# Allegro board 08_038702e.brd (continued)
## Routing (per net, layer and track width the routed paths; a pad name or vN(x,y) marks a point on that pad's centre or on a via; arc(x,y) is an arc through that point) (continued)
IO_25_12_JX4: length 68.8
  TOP w0.14: U1.W17 v1(28.22,26.59)
  L4_SIG w0.095: v3(80.22,45.07) 80.12,44.97 74.09,44.97 73.71,44.59 73.71,44.05 73.33,43.67 57.28,43.67 57.13,43.82 54.81,43.82 54.66,43.67 54.15,43.67 54.03,43.54 53.39,43.54 53.1,43.84 50,43.84 49.99,43.82 49.65,43.82 49.45,43.62 49.45,43.29 48.31,42.15 43.99,42.15 43.61,41.76 43.61,40.37 43.36,40.11 41.2,40.11 40.56,39.47 40.56,39.45 40.36,39.25 40.34,39.25 39.88,38.79 39.88,38.66 39.14,37.93 39.07,37.93 38.88,37.73 38.88,37.66 38.46,37.25 37.32,37.25 37.14,37.07 30.02,37.07 29.89,36.93 29.07,36.93 28.74,36.6 28.7,36.6 28.21,36.1 28.21,36.06 27.88,35.73 27.88,34.92 27.74,34.78 27.74,26.97 28.12,26.59 v1(28.22,26.59)
  L19_GND w0.203: v3(80.22,45.07) 80.82,45.07 v4(80.82,45.07)
IO_25_13_JX2: length 72.3
  TOP w0.14: U1.V18 v1(29.22,25.59)
  L18_SIG w0.095: v1(35.36,8.24) 35.33,8.26 33.48,8.26 31.93,6.71 31.93,6.46 32.06,6.33 32.56,6.33 33.96,7.73 34.47,7.73 34.72,7.48 34.72,7.34 33.83,6.46 33.83,6.17 33.93,6.08 34.85,6.08 35.36,6.59 40.69,6.59 40.82,6.46 40.82,6.18 40.69,6.05 35.87,6.05 35.26,5.44 32.31,5.44 31.04,6.71 28.8,6.71 28.16,6.08 27.48,6.08 27.23,6.33 26.09,6.33 24.55,7.87 24.52,7.87 24.33,8.07 24.33,8.09 24.18,8.24 24.18,9.13 23.8,9.51 23.29,9.51 22.91,9.89 22.91,10.6 23.29,10.98 24.77,10.98 25.71,11.92 28.47,11.92 28.64,11.75 28.71,11.68 30.8,11.68 31.17,12.05 31.17,13.06 30.79,13.44 30.28,13.44 29.52,14.21 29.52,14.59 28.33,15.77 28.33,16.63 28.13,16.83 27.02,16.83 26.6,17.25 26.6,18.69 26.36,18.93 24.92,18.93 24.56,19.29 24.56,23.42 25.07,23.93 25.36,23.93 25.55,24.13 25.55,24.41 26.4,25.25 28.36,25.25 28.36,25.25 28.88,25.25 v1(29.22,25.59)
  BOTTOM w0.14: v1(35.36,8.24) 35.49,8.24 35.93,7.79 JX2.14
IO_25_33_JX1: length 72.6
  TOP w0.14: U1.N8 v1(35.22,36.59)
  L7_SIG w0.095: v1(34.33,49.65) 34.34,49.67 34.34,53.7 33.96,54.08 31.42,54.08 30.53,54.97 30.53,57.89 30.91,58.27 33.23,58.27 33.25,58.3 33.53,58.3 33.55,58.27 37.26,58.27 37.64,58.66 37.64,59.42 37.26,59.8 29.81,59.8 29.56,59.54 27.36,59.54 26.98,59.16 24.44,59.16 24.06,59.54 22.28,59.54 21.9,59.16 21.9,58.4 22.4,57.89 29.26,57.89 29.52,57.64 29.52,54.72 30.41,53.83 33.58,53.83 33.96,53.45 33.96,49.13 34.33,48.76 34.33,45.15 34.26,45.08 34.26,44.8 34.33,44.73 34.33,39.84 33.71,39.22 33.71,38.1 v1(35.22,36.59)
  BOTTOM w0.14: JX1.10 v1(34.33,49.65)
IO_25_34_JX4: length 50.5
  TOP w0.14: U1.K10 v1(38.22,34.59)
  L14_SIG w0.095: v1(38.22,34.59) 38.22,34.59 38.66,34.14 44.25,34.14 44.56,34.45 44.56,34.45 45.26,35.16 50.37,35.16 50.45,35.08 50.73,35.08 50.82,35.16 51.17,35.16 51.25,35.08 51.53,35.08 51.62,35.16 59.21,35.16 59.85,35.8 68.89,35.8 71.81,32.87 75.24,32.87 78.67,29.45 78.67,27.3 v1(80.2,25.77)
  BOTTOM w0.14: JX4.64 v1(80.2,25.77)
IO_25_35_AD9361_CLKOUT: length 31.8
  TOP w0.14: v6(66,32.09) U17.J6 ; U1.K12 v1(38.22,32.59)
  L4_SIG w0.095: v1(38.22,32.59) 38.82,31.99 39.17,31.99 39.23,31.93 39.36,31.93 39.55,31.73 39.55,31.6 41.07,30.08 47.55,30.08 48.82,31.35 53.93,31.35 54.14,31.14 54.42,31.14 54.63,31.35 56.72,31.35 56.85,31.22 57.06,31.01 57.34,31.01 57.56,31.22 59.74,31.22 60.12,30.84 63.85,30.84 64.7,31.69 65.59,31.69 v6(66,32.09)
IO_L01_12_JX3_N: length 72.3
  TOP w0.089: U1.Y11 v1(27.22,33.59)
  L18_SIG w0.089: v1(27.22,33.59) 26.81,33.18 20.34,33.18 19.99,32.83 19.99,32.34 20.34,32 25.35,32 25.58,31.77 25.58,31.6 25.55,31.58 25.55,31.45 25.35,31.25 25.23,31.25 25.2,31.22 19.98,31.22 19.61,30.85 19.61,30.33 19.98,29.95 25.33,29.95 25.55,29.73 25.55,29.42 25.33,29.19 20.63,29.19 20.25,28.81 20.25,28.3 20.62,27.93 25.35,27.93 25.55,27.73 25.55,27.38 25.35,27.18 20.77,27.18 20.25,26.65 20.25,25.11 19.95,24.81 19.95,24.35 19.75,24.16 17.42,24.16 17.07,23.81 17.07,23.32 17.42,22.97 18.74,22.97 18.98,22.74 18.98,22.31 18.74,22.08 15.69,22.08 15.17,21.56 15.17,20.82 15.69,20.3 18.75,20.3 18.98,20.08 18.98,19.76 18.59,19.38 18.59,18.76 18.36,18.52 17.81,18.52 17.58,18.76 17.58,19.01 17.05,19.54 16.23,19.54 15.2,18.5 14.53,18.5 14.15,18.88 v1(14.15,19.06)
  BOTTOM w0.089: JX3.22 13.17,19.37 13.49,19.06 v1(14.15,19.06)
IO_L01_12_JX3_P: length 72.3
  TOP w0.089: U1.Y12 v1(27.22,32.59)
  L18_SIG w0.089: v1(13.77,18.65) 13.98,18.65 14.49,18.14 14.66,18.14 14.76,18.25 15.3,18.25 16.34,19.29 16.94,19.29 17.32,18.9 17.32,18.65 17.71,18.27 18.47,18.27 18.85,18.65 18.85,19.28 19.23,19.66 19.23,20.18 18.86,20.56 15.79,20.56 15.42,20.93 15.42,21.45 15.79,21.83 18.85,21.83 19.23,22.21 19.23,22.84 18.85,23.22 17.52,23.22 17.32,23.42 17.32,23.7 17.52,23.9 19.86,23.9 20.2,24.25 20.2,24.7 20.5,25 20.5,26.55 20.88,26.93 25.46,26.93 25.81,27.27 25.81,27.83 25.46,28.18 20.73,28.18 20.5,28.41 20.5,28.71 20.73,28.94 25.43,28.94 25.81,29.31 25.81,29.83 25.43,30.21 20.09,30.21 19.86,30.43 19.86,30.75 20.09,30.97 25.3,30.97 25.33,31 25.46,31 25.81,31.34 25.81,31.47 25.83,31.5 25.83,31.88 25.46,32.25 20.44,32.25 20.25,32.45 20.25,32.73 20.44,32.93 26.88,32.93 v1(27.22,32.59)
  BOTTOM w0.089: JX3.20 13.18,18.57 13.45,18.84 13.58,18.84 v1(13.77,18.65)
IO_L01_13_JX2_N: length 72.9
  TOP w0.089: U1.AB25 v1(25.22,18.59)
  L18_SIG w0.089: v1(25.22,18.59) 25.59,18.22 25.59,18.13 25.55,18.09 25.55,17.45 25.35,17.25 23.14,17.25 23.14,17.25 23.08,17.25 22.88,17.45 22.88,17.73 22.91,17.76 22.91,18.42 22.88,18.45 22.88,18.73 22.91,18.76 22.91,19.42 22.88,19.45 22.88,19.73 22.91,19.76 22.91,20.42 22.88,20.45 22.88,20.73 22.91,20.76 22.91,21.42 22.88,21.45 22.88,21.73 22.91,21.76 22.91,22.42 22.88,22.45 22.88,22.68 22.81,22.76 22.81,22.83 22.46,23.18 22.38,23.18 21.9,23.18 21.63,22.91 21.63,16.22 21.52,16.11 21.36,16.11 21.27,16.03 20.99,16.03 20.91,16.11 19.83,16.11 19.75,16.03 19.47,16.03 19.39,16.11 17.96,16.11 17.71,15.86 17.71,15.22 17.96,14.97 24.46,14.97 24.56,14.86 24.56,14.44 24.46,14.33 18.02,14.33 17.87,14.19 17.54,14.19 17.35,14.38 16.93,14.38 16.85,14.46 13.01,14.46 12.75,14.21 12.75,13.32 13.01,13.06 26.5,13.06 26.88,13.44 26.88,16.01 26.98,16.11 27.54,16.11 27.61,16.04 27.61,14.97 28.08,14.5 28.47,14.5 28.63,14.35 v3(28.63,12.55)
  L19_GND w0.089: v3(28.63,12.55) 28.75,12.43 v4(28.75,12.05)
  BOTTOM w0.089: JX2.3 31.93,10.14 31.68,9.89 31.68,9.51 31.29,9.13 30.41,9.13 28.88,10.65 28.88,11.92 v4(28.75,12.05)
IO_L01_13_JX2_P: length 72.8
  TOP w0.089: U1.AA25 v1(26.22,18.59)
  L18_SIG w0.089: v1(26.22,18.59) 25.84,18.22 25.84,18.02 25.81,17.98 25.81,17.34 25.46,17 23.04,17 22.97,17 22.63,17.34 22.63,17.83 22.66,17.87 22.66,18.31 22.63,18.34 22.63,18.83 22.66,18.87 22.66,19.31 22.63,19.34 22.63,19.83 22.66,19.87 22.66,20.31 22.63,20.34 22.63,20.83 22.66,20.87 22.66,21.31 22.63,21.34 22.63,21.83 22.66,21.87 22.66,22.31 22.63,22.34 22.63,22.58 22.55,22.65 22.55,22.73 22.35,22.92 22.28,22.92 22.02,22.93 21.88,22.78 21.88,16.12 21.62,15.86 21.46,15.86 21.38,15.77 20.89,15.77 20.81,15.86 19.94,15.86 19.86,15.77 19.37,15.77 19.28,15.86 18.06,15.86 17.96,15.75 17.96,15.33 18.06,15.22 24.56,15.22 24.82,14.97 24.82,14.33 24.56,14.08 18.12,14.08 17.98,13.93 17.43,13.93 17.24,14.12 16.83,14.12 16.74,14.21 13.11,14.21 13.01,14.1 13.01,13.42 13.11,13.32 26.39,13.32 26.62,13.55 26.62,16.11 26.88,16.36 27.66,16.36 27.66,16.35 27.87,16.14 27.87,15.07 28.18,14.75 28.58,14.75 28.88,14.45 28.88,13.44 29.14,13.19 29.52,13.19 29.64,13.06 29.64,12.94 v3(29.26,12.55)
  L19_GND w0.089: v3(29.26,12.55) 29.1,12.39 v4(29.1,12.05)
  BOTTOM w0.089: v4(29.1,12.05) 29.1,10.74 30.49,9.34 31.2,9.34 31.46,9.6 31.46,9.88 31.13,10.21 JX2.1
IO_L01_33_JX1_N: length 72.3
  TOP w0.089: U1.F4 v1(42.22,40.59)
  L3_SIG w0.089: v1(42.22,40.59) 41.84,40.96 41.84,43.83 42.32,44.3 42.96,44.3 43.51,44.86 43.51,45.24 45.13,46.86 45.25,46.86 46.31,47.91 47.09,47.91 49.2,50.02 66.22,50.02 66.6,50.4 66.6,53.12 66.81,53.33 66.81,53.65 67.09,53.93 67.09,54.68 66.73,55.05 66.73,55.5 67.11,55.88 67.24,55.88 67.62,56.26 67.62,56.73 67.24,57.11 67.02,57.11 66.88,57.26 66.88,57.56 67.36,58.04 67.36,58.78 66.98,59.16 63.77,59.16 63.69,59.08 59.72,59.08 59.53,58.89 57.86,58.89 57.33,59.42 56.44,59.42 56.06,59.04 56.06,58.13 55.83,57.89 55.4,57.89 55.17,58.13 55.17,58.91 54.79,59.29 53.86,59.29 53.47,58.91 53.47,58.01 53.28,57.81 53.27,57.81 53.12,57.66 53.12,55.99 52.74,55.61 45.65,55.61 45.26,55.99 45.26,56.62 v1(45.52,56.88)
  BOTTOM w0.089: v1(45.52,56.88) 45.26,56.62 45.26,56.37 45.53,56.11 JX1.37
IO_L01_33_JX1_P: length 72.3
  TOP w0.089: U1.G4 v1(41.22,40.59)
  L3_SIG w0.089: v1(44.76,56.88) 45.01,56.62 45.01,55.88 45.54,55.35 52.84,55.35 53.37,55.88 53.37,57.55 53.73,57.9 53.73,58.8 53.96,59.04 54.68,59.04 54.92,58.8 54.92,58.02 55.3,57.64 55.93,57.64 56.31,58.02 56.31,58.93 56.55,59.16 57.22,59.16 57.75,58.64 59.63,58.64 59.82,58.83 63.8,58.83 63.88,58.91 66.88,58.91 67.11,58.68 67.11,58.15 66.62,57.66 66.62,57.15 66.92,56.86 67.13,56.86 67.36,56.62 67.36,56.37 67.13,56.14 67,56.14 66.47,55.61 66.47,54.94 66.84,54.58 66.84,54.04 66.56,53.75 66.56,53.44 66.35,53.23 66.35,50.51 66.11,50.27 49.1,50.27 46.99,48.17 46.21,48.17 45.15,47.11 45.02,47.11 43.25,45.34 43.25,44.96 42.85,44.56 42.22,44.56 41.59,43.93 41.59,40.96 v1(41.22,40.59)
  BOTTOM w0.089: JX1.35 44.73,56.09 45.01,56.37 45.01,56.62 v1(44.76,56.88)
IO_L01_34_JX4_N: length 71.9
  TOP w0.089: U1.H11 v1(40.22,33.59)
  L17_SIG w0.089: v1(84.38,42.53) 84.38,42.78 84.13,43.03 83.92,43.03 83.85,42.96 83.62,42.96 83.54,43.03 83.26,43.03 82.48,43.82 82.48,47.84 82.39,47.93 82.39,48.6 82.3,48.7 82.3,52 81.23,53.07 80.57,53.07 80.06,52.56 79.05,52.56 78.54,53.07 77.52,53.07 76.31,51.85 75.11,51.85 75.1,51.84 74.61,51.84 74.6,51.85 72.27,51.85 72.2,51.92 69.05,51.92 69,51.87 68.46,51.87 68.4,51.92 65.14,51.92 65,51.78 64.46,51.78 64.35,51.88 58.12,51.88 58.08,51.84 57.59,51.84 57.55,51.88 50.86,51.88 50.82,51.92 48.93,51.92 45.14,48.14 45.14,47.37 43.72,45.96 41.49,45.96 40.61,45.08 40.61,44.88 39.84,44.11 39.84,33.96 v1(40.22,33.59)
  BOTTOM w0.089: JX4.21 85.01,42.57 84.78,42.8 84.65,42.8 v1(84.38,42.53)
IO_L01_34_JX4_P: length 72
  TOP w0.089: U1.J11 v1(39.22,33.59)
  L17_SIG w0.089: v1(84.38,43.29) 83.36,43.29 82.73,43.92 82.73,47.95 82.65,48.03 82.65,48.71 82.55,48.81 82.55,52.1 81.33,53.32 80.46,53.32 79.96,52.81 79.15,52.81 78.64,53.32 77.42,53.32 76.2,52.11 75.01,52.11 74.99,52.1 74.72,52.1 74.7,52.11 72.37,52.11 72.3,52.18 68.94,52.18 68.89,52.13 68.56,52.13 68.51,52.18 65.04,52.18 64.89,52.03 64.56,52.03 64.46,52.14 58.02,52.14 57.98,52.1 57.7,52.1 57.66,52.14 50.96,52.14 50.92,52.18 48.82,52.18 44.88,48.24 44.88,47.48 43.61,46.21 41.38,46.21 40.36,45.18 40.36,44.98 39.59,44.22 39.59,33.96 v1(39.22,33.59)
  BOTTOM w0.089: v1(84.38,43.29) 84.63,43.03 84.76,43.03 85.1,43.37 JX4.19
IO_L01_35_RX_D0_N: length 43.1
  TOP w0.089: U1.E12 v1(43.22,32.59) ; v6(61.2,32.89) U17.K11
  L4_SIG w0.089: v1(43.22,32.59) 43.13,32.67 42.95,32.67 42.87,32.59 42.87,32.24 42.8,32.17 42.55,31.92 40.92,31.92 40.82,31.82 40.82,31.36 40.92,31.25 42.58,31.25 42.85,30.98 42.85,30.71 42.98,30.59 43.16,30.59 43.28,30.71 43.28,31.18 43.55,31.45 43.55,31.83 43.97,32.25 44.46,32.25 44.88,31.83 44.88,31.45 45.08,31.25 45.16,31.25 45.16,31.25 45.62,31.25 45.9,30.98 45.9,30.72 46.03,30.59 46.48,30.59 46.61,30.72 46.61,30.98 46.89,31.25 47.88,31.25 47.98,31.36 47.98,31.76 48.31,32.09 51.94,32.09 52.2,32.34 52.2,32.93 52.47,33.2 52.89,33.2 53.16,32.93 53.16,32.21 53.29,32.09 53.52,32.09 53.65,32.21 53.65,33.49 53.92,33.76 54.77,33.76 55.04,33.49 55.04,31.96 55.17,31.83 56.31,31.83 56.44,31.96 56.44,33.51 56.69,33.76 57.2,33.76 57.46,33.51 57.46,32.04 57.56,31.93 57.99,31.93 58.09,32.04 58.09,33.51 58.35,33.76 59.9,33.76 60.15,33.52 60.15,33.17 59.9,32.93 59.49,32.93 59.36,32.8 59.36,31.88 59.48,31.76 59.65,31.76 59.77,31.88 59.77,32.32 60.04,32.59 60.76,32.59 60.94,32.42 61.32,32.42 61.39,32.49 61.39,32.7 v6(61.2,32.89)
IO_L01_35_RX_D0_P: length 43.2
  TOP w0.089: v6(60.4,32.09) U17.J12 ; U1.F12 v1(42.22,32.59)
  L4_SIG w0.089: v6(60.4,32.09) 60.57,31.92 60.69,31.92 60.82,32.05 60.82,32.18 60.66,32.34 60.15,32.34 60.02,32.21 60.02,31.77 59.75,31.5 59.38,31.5 59.11,31.77 59.11,32.9 59.38,33.18 59.8,33.18 59.89,33.28 59.89,33.41 59.8,33.51 58.45,33.51 58.35,33.4 58.35,31.93 58.09,31.68 57.46,31.68 57.2,31.93 57.2,33.4 57.1,33.51 56.8,33.51 56.69,33.4 56.69,31.85 56.42,31.58 55.06,31.58 54.79,31.85 54.79,33.38 54.66,33.51 54.03,33.51 53.9,33.38 53.9,32.11 53.62,31.83 53.19,31.83 52.91,32.11 52.91,32.82 52.78,32.95 52.58,32.95 52.45,32.82 52.45,32.24 52.05,31.83 48.42,31.83 48.24,31.65 48.24,31.25 47.98,31 46.99,31 46.86,30.87 46.86,30.61 46.59,30.33 45.92,30.33 45.65,30.61 45.65,30.87 45.52,31 45.06,31 44.97,31 44.63,31.34 44.63,31.73 44.35,32 44.08,32 43.81,31.73 43.81,31.34 43.54,31.08 43.54,30.61 43.26,30.33 42.87,30.33 42.6,30.61 42.6,30.87 42.47,31 40.82,31 40.57,31.25 40.57,31.92 40.82,32.18 41.81,32.18 41.82,32.19 42.46,32.19 42.62,32.35 42.62,32.58 42.5,32.7 42.32,32.7 v1(42.22,32.59)
IO_L02_12_JX3_N: length 72.4
  TOP w0.089: U1.AC11 v1(24.22,33.59)
  L6_SIG w0.089: v1(24.22,33.59) 24.56,33.24 24.56,33.12 24.37,32.93 24.08,32.93 23.88,32.73 23.88,32.32 23.74,32.18 20.9,32.18 20.07,31.35 19.12,31.35 18.74,30.97 15.69,30.97 14.02,29.3 14.02,22.18 13.6,21.76 13.54,21.76 13.01,21.23 13.01,10.37 12.77,10.14 12.48,10.14 12.24,10.37 12.24,10.63 11.71,11.16 10.16,11.16 10.08,11.24 8.82,11.24 8.48,10.89 8.48,10.4 8.59,10.29 8.59,7.86 8.34,7.6 7.93,7.6 7.67,7.86 7.67,8.49 7.42,8.74 4.48,8.74 4.37,8.85 4.37,9.66 4.48,9.76 7.4,9.76 7.8,10.16 7.8,15.5 8.03,15.73 8.46,15.73 8.69,15.5 8.69,15.37 9.22,14.84 10.24,14.84 10.34,14.75 10.83,14.75 10.92,14.84 11.71,14.84 12.24,15.37 12.24,21.23 11.75,21.72 11.54,21.72 11.33,21.72 11.23,21.83 11.08,21.83 10.97,21.72 10.69,21.72 v1(10.47,21.95)
  BOTTOM w0.089: JX3.27 8.96,21.77 9.2,21.53 9.58,21.53 9.7,21.66 9.79,21.66 9.83,21.7 10.21,21.7 v1(10.47,21.95)
IO_L02_12_JX3_P: length 72.4
  TOP w0.089: U1.AB12 v1(25.22,32.59)
  L6_SIG w0.089: v1(25.22,32.59) 24.87,32.94 24.74,32.94 24.67,32.87 24.67,32.57 24.24,32.14 24.06,32.14 23.85,31.93 21.01,31.93 20.18,31.1 19.23,31.1 18.85,30.72 15.8,30.72 14.28,29.19 14.28,22.08 13.7,21.51 13.64,21.51 13.26,21.13 13.26,10.27 12.88,9.89 12.37,9.89 11.99,10.27 11.99,10.52 11.61,10.9 10.05,10.9 9.97,10.99 8.93,10.99 8.73,10.79 8.73,10.51 8.85,10.4 8.85,7.75 8.44,7.35 7.82,7.35 7.42,7.75 7.42,8.39 7.31,8.49 4.37,8.49 4.12,8.74 4.12,9.76 4.37,10.01 7.29,10.01 7.55,10.27 7.55,15.6 7.93,15.98 8.56,15.98 8.94,15.6 8.94,15.48 9.32,15.09 10.35,15.09 10.44,15 10.72,15 10.82,15.09 11.61,15.09 11.99,15.48 11.99,21.13 11.65,21.47 11.54,21.47 10.62,21.47 v1(10.47,21.32)
  BOTTOM w0.089: v1(10.47,21.32) 10.34,21.44 9.79,21.44 9.67,21.32 9.2,21.32 8.85,20.97 JX3.25
IO_L02_13_JX2_N: length 72.8
  TOP w0.089: U1.AC26 v1(24.22,17.59)
  L7_SIG w0.089: v1(24.22,17.59) 24.55,17.93 24.55,21.73 24.35,21.93 24.35,21.93 24.32,21.95 23.14,21.95 23.12,21.93 23.08,21.93 22.88,21.73 22.88,21.45 23.15,21.18 23.46,21.18 23.88,20.76 23.88,19.31 23.5,18.93 22.02,18.93 21.88,18.78 21.88,13.38 22.11,13.15 25.06,13.15 25.99,12.22 26.35,12.22 26.56,12.43 27.52,12.43 27.75,12.19 29.62,12.19 30.66,11.16 32.2,11.16 32.59,11.54 39.42,11.54 39.8,11.16 39.8,10.35 39.42,9.97 39.02,9.97 38.79,9.74 38.79,6.97 39.04,6.71 39.42,6.71 39.68,6.46 39.68,4.3 39.93,4.05 43.74,4.05 43.99,3.79 43.99,3.18 43.59,2.78 38.81,2.78 38.41,3.18 38.41,5.46 38.3,5.57 38.05,5.57 37.64,5.97 37.64,6.86 37.54,6.97 36.4,6.97 35.99,7.37 35.99,9.59 35.61,9.97 32.29,9.97 31.55,9.23 31.55,9 31.68,8.87 31.93,8.87 32.06,8.74 32.06,8.49 31.93,8.36 31.68,8.36 31.55,8.24 31.55,8.11 v1(31.8,7.86)
  BOTTOM w0.089: JX2.4 31.93,7.35 31.68,7.6 31.68,7.73 v1(31.8,7.86)
IO_L02_13_JX2_P: length 72.8
  TOP w0.089: U1.AB26 v1(25.22,17.59)
  L7_SIG w0.089: v1(31.29,7.86) 31.29,9.34 32.18,10.22 35.72,10.22 36.25,9.69 36.25,7.47 36.5,7.22 37.64,7.22 37.9,6.97 37.9,6.08 38.15,5.82 38.41,5.82 38.66,5.57 38.66,3.28 38.91,3.03 43.49,3.03 43.74,3.28 43.74,3.69 43.63,3.79 39.82,3.79 39.42,4.19 39.42,6.35 39.32,6.46 38.94,6.46 38.53,6.86 38.53,9.84 38.91,10.22 39.32,10.22 39.55,10.46 39.55,11.05 39.32,11.28 32.69,11.28 32.31,10.9 30.55,10.9 29.52,11.94 27.65,11.94 27.41,12.17 26.67,12.17 26.46,11.96 25.88,11.96 24.96,12.89 22.01,12.89 21.62,13.27 21.62,18.89 21.92,19.18 23.39,19.18 23.62,19.41 23.62,20.66 23.35,20.93 23.04,20.93 22.62,21.34 22.62,21.83 22.97,22.18 23.01,22.18 23.04,22.21 24.42,22.21 24.45,22.18 24.46,22.18 24.81,21.83 24.81,18 v1(25.22,17.59)
  BOTTOM w0.089: v1(31.29,7.86) 31.42,7.73 31.42,7.6 31.13,7.31 JX2.2
IO_L02_33_JX1_N: length 73.9
  TOP w0.089: U1.D3 v1(44.22,41.59)
  L3_SIG w0.089: v1(47.93,57.39) 47.63,57.09 47.63,56.8 48.06,56.37 50.6,56.37 50.98,56.75 50.98,58.17 50.75,58.4 49.96,58.4 49.58,58.78 49.58,59.93 49.96,60.31 51.36,60.31 51.49,60.18 67.59,60.18 68.63,59.14 68.63,56.75 68.38,56.5 68.38,54.14 68.33,54.09 68.33,53.76 68.38,53.71 68.38,52.74 68.33,52.69 68.33,52.36 68.38,52.31 68.38,49.28 67.34,48.24 60.01,48.24 59.96,48.19 59.47,48.19 59.42,48.24 55.06,48.24 54.94,48.37 54.01,48.37 53.88,48.24 48.31,48.24 47.3,47.23 47.3,45.7 45.65,44.05 44.48,44.05 44.36,43.92 43.97,43.92 43.81,43.76 43.81,43.34 43.46,43 43.05,43 42.85,42.8 42.85,41.48 43.08,41.25 43.72,41.25 43.75,41.22 43.95,41.22 43.98,41.18 44.15,41.18 44.22,41.25 v1(44.22,41.59)
  BOTTOM w0.089: JX1.43 47.93,56.25 47.68,56.5 47.68,57.13 v1(47.93,57.39)
IO_L02_33_JX1_P: length 74
  TOP w0.089: U1.D4 v1(44.22,40.59)
  L3_SIG w0.089: v1(47.3,57.39) 47.38,57.3 47.38,56.69 47.95,56.12 50.7,56.12 51.23,56.65 51.23,58.27 50.85,58.66 50.07,58.66 49.84,58.89 49.84,59.82 50.07,60.05 51.25,60.05 51.38,59.93 67.49,59.93 68.38,59.04 68.38,56.86 68.12,56.6 68.12,54.25 68.07,54.2 68.07,53.65 68.12,53.6 68.12,52.85 68.07,52.8 68.07,52.26 68.12,52.21 68.12,49.38 67.24,48.5 59.9,48.5 59.85,48.44 59.57,48.44 59.52,48.5 55.17,48.5 55.04,48.62 53.9,48.62 53.77,48.5 48.21,48.5 47.04,47.33 47.04,45.81 45.54,44.3 44.38,44.3 44.25,44.18 43.87,44.18 43.55,43.86 43.55,43.45 43.35,43.25 42.94,43.25 42.6,42.91 42.6,41.37 42.97,41 43.61,41 43.65,40.96 43.84,40.96 v1(44.22,40.59)
  BOTTOM w0.089: JX1.41 47.13,56.2 47.42,56.5 47.42,57.13 47.3,57.26 v1(47.3,57.39)
IO_L02_34_JX4_N: length 74.2
  TOP w0.089: U1.G5 v1(41.22,39.59)
  L4_SIG w0.089: v1(41.22,39.59) 41.59,39.22 43.32,39.22 43.55,39.45 43.55,39.8 43.99,40.24 48.06,40.24 49.84,42.02 50.26,42.02 50.45,42.22 50.73,42.22 50.93,42.02 51.06,42.02 51.25,42.22 51.53,42.22 51.73,42.02 52.03,42.02 52.24,42.23 52.52,42.23 52.73,42.02 54.66,42.02 55.3,42.65 55.93,42.65 56.82,41.76 57.58,41.76 57.71,41.89 61.41,41.89 61.92,42.4 63.77,42.4 64.28,41.89 73.33,41.89 73.97,42.53 74.22,42.78 74.96,42.78 75.6,42.15 76.65,42.15 76.92,42.41 76.92,42.5 77.29,42.87 77.38,42.87 77.45,42.95 77.46,42.95 77.78,43.27 77.78,43.65 78.31,44.18 80.57,44.18 80.95,44.56 80.95,51.8 80.57,52.18 79.43,52.18 79.02,52.58 79.02,53.43 79.43,53.83 81.69,53.83 82.22,53.3 82.22,52.05 82.6,51.67 82.73,51.67 83.11,51.29 83.11,49.89 82.73,49.51 82.6,49.51 82.22,49.13 82.22,43.16 81.71,42.65 v1(80.19,42.65)
  BOTTOM w0.089: JX4.22 80.81,42.57 80.52,42.86 80.4,42.86 v1(80.19,42.65)
IO_L02_34_JX4_P: length 74.2
  TOP w0.089: U1.G6 v1(41.22,38.59)
  L4_SIG w0.089: v1(80.19,43.29) 80.19,43.13 80.41,42.91 80.7,42.91 80.82,43.03 80.82,43.42 80.95,43.54 81.21,43.54 81.33,43.42 81.33,43.03 81.46,42.91 81.61,42.91 81.97,43.27 81.97,49.24 82.5,49.77 82.62,49.77 82.86,50 82.86,51.18 82.62,51.42 82.5,51.42 81.97,51.95 81.97,53.19 81.59,53.58 79.53,53.58 79.28,53.32 79.28,52.69 79.53,52.43 80.68,52.43 81.21,51.9 81.21,44.45 80.68,43.92 78.41,43.92 78.03,43.54 78.03,43.16 77.56,42.69 77.56,42.69 77.48,42.62 77.4,42.62 77.17,42.4 77.17,42.3 76.76,41.89 75.49,41.89 74.86,42.53 74.33,42.53 74.07,42.27 73.44,41.64 64.17,41.64 63.67,42.15 62.03,42.15 61.52,41.64 57.96,41.64 57.79,41.46 56.33,41.46 56.28,41.42 56,41.42 55.88,41.54 55.05,41.54 54.98,41.6 54.82,41.76 52.73,41.76 52.52,41.55 52.24,41.55 52.03,41.76 51.75,41.76 51.53,41.54 51.25,41.54 51.03,41.76 50.95,41.76 50.73,41.54 50.45,41.54 50.23,41.76 49.94,41.76 48.16,39.99 44.1,39.99 43.81,39.69 43.81,39.34 43.42,38.96 41.59,38.96 v1(41.22,38.59)
  BOTTOM w0.089: JX4.20 80.78,43.37 80.51,43.1 80.38,43.1 v1(80.19,43.29)
IO_L02_35_RX_D1_N: length 43.8
  TOP w0.089: U1.D10 v1(44.22,34.59) ; v6(62,32.89) U17.K10
  L17_SIG w0.089: v6(62,32.89) 61.85,32.75 61.65,32.75 61.52,32.88 61.52,33 61.32,33.19 61.05,33.19 60.7,33.55 60.7,33.82 60.52,33.99 60.41,33.99 59.36,35.03 58.49,35.03 57.99,34.53 57.38,34.53 57.13,34.28 57.05,34.28 56.82,34.05 56.82,33.64 57.08,33.38 59.11,33.38 59.36,33.13 59.36,32.85 59.26,32.74 59.03,32.74 58.87,32.58 58.59,32.58 58.42,32.74 55.25,32.74 54.76,33.23 54.76,34.53 54.51,34.78 53.92,34.78 53.52,34.38 53.52,32.81 53.41,32.7 52.99,32.7 52.88,32.81 52.88,35.16 52.63,35.41 52,35.41 51.74,35.16 51.74,33.71 51.64,33.61 50.69,33.61 50.69,33.6 49.55,33.6 49.18,33.24 48.31,33.24 47.93,33.61 47.93,34.17 48.31,34.55 48.31,36.3 48.06,36.56 47.71,36.56 47.34,36.18 46.97,36.18 46.97,36.18 46.88,36.18 46.63,35.92 46.63,34.74 46.55,34.67 46.55,34.45 46.53,34.43 46.53,33.74 46.55,33.73 46.55,33.45 46.35,33.25 46.29,33.25 46.28,33.24 46.15,33.24 46.14,33.25 46.08,33.25 45.88,33.45 45.88,33.83 45.46,34.25 44.97,34.25 44.55,33.83 44.55,33.45 44.35,33.25 44.26,33.25 44.25,33.24 44.07,33.24 43.84,33.47 43.84,34.22 v1(44.22,34.59)
IO_L02_35_RX_D1_P: length 44.1
  TOP w0.089: v6(61.2,32.09) U17.J11 ; U1.E10 v1(43.22,34.59)
  L17_SIG w0.089: v6(61.2,32.09) 61.39,32.29 61.39,32.49 61.32,32.56 61.1,32.56 60.88,32.78 60.88,33 60.51,33.38 60.29,33.38 60.08,33.58 60.08,33.8 59.97,33.92 59.97,34.14 59.33,34.78 58.6,34.78 58.09,34.27 57.48,34.27 57.24,34.02 57.15,34.02 57.08,33.95 57.08,33.74 57.18,33.64 59.21,33.64 59.62,33.23 59.62,32.74 59.36,32.49 59.14,32.49 58.97,32.32 58.48,32.32 58.32,32.49 55.15,32.49 54.51,33.13 54.51,34.42 54.41,34.53 54.03,34.53 53.77,34.27 53.77,32.75 53.52,32.49 52.88,32.49 52.63,32.75 52.63,35.06 52.52,35.16 52.1,35.16 52,35.06 52,33.61 51.74,33.35 50.8,33.35 50.8,33.35 49.65,33.35 49.29,32.99 48.2,32.99 47.68,33.51 47.68,34.27 48.06,34.65 48.06,36.2 47.95,36.3 47.82,36.3 47.44,35.92 47.08,35.92 47.07,35.92 46.98,35.92 46.88,35.82 46.88,34.64 46.81,34.56 46.81,34.34 46.79,34.33 46.79,33.85 46.81,33.83 46.81,33.34 46.46,33 46.4,33 46.39,32.99 46.05,32.99 46.03,33 45.97,33 45.63,33.34 45.63,33.73 45.35,34 45.08,34 44.81,33.73 44.81,33.34 44.46,33 44.37,33 44.35,32.99 43.97,32.99 43.59,33.36 43.59,34.22 v1(43.22,34.59)
IO_L03_12_JX3_N: length 73.2
  TOP w0.089: U1.AA10 v1(26.22,34.59)
  L18_SIG w0.089: v1(26.22,34.59) 26.59,34.96 26.59,35.16 26.6,35.16 26.6,36.8 26.98,37.19 29.54,37.19 29.56,37.21 29.56,38.73 29.63,38.8 29.63,41.91 29.54,42 28.89,42 28.81,41.91 28.81,38.34 28.46,38 28.4,38 28.33,37.94 27.02,37.94 26.6,38.36 26.6,41.68 26.55,41.73 26.35,41.92 26.08,41.92 26.07,41.91 25.98,41.91 25.83,41.77 25.83,34.37 25.81,34.34 25.46,34 25.25,34 24.97,34 24.62,34.34 24.62,37.83 24.69,37.9 24.69,38.28 24.62,38.34 24.62,38.83 24.69,38.9 24.69,39.28 24.62,39.34 24.62,40.83 24.46,41 24.07,41 23.81,40.73 23.81,40.34 23.8,40.34 23.8,39.84 23.81,39.83 23.81,39.34 23.8,39.34 23.8,38.84 23.81,38.83 23.81,38.34 23.8,38.34 23.8,37.84 23.81,37.83 23.81,37.34 23.8,37.34 23.8,36.84 23.81,36.83 23.81,36.34 23.46,36 22.95,36 22.55,36.4 22.55,38.1 22.45,38.21 21.87,38.21 21.77,38.1 21.77,36.33 21.37,35.92 21.08,35.92 20.63,35.48 20.63,34.29 19.97,33.64 19.21,33.64 18.59,33.02 18.59,31.71 19.23,31.07 19.23,25.89 18.47,25.13 16.82,25.13 16.18,24.49 15.27,24.49 14.13,23.35 14.13,22.48 14.28,22.33 14.53,22.33 14.66,22.21 14.66,22.08 14.53,21.95 14.28,21.95 14.13,21.81 14.13,21.64 14.46,21.32 v1(14.66,21.32)
  BOTTOM w0.089: v1(14.66,21.32) 14.2,21.32 13.98,21.53 13.64,21.53 13.4,21.77 JX3.28
IO_L03_12_JX3_P: length 73.3
  TOP w0.089: U1.Y10 v1(27.22,34.59)
  L18_SIG w0.089: v1(14.28,20.94) 14.28,21.14 13.88,21.54 13.88,23.46 15.17,24.75 16.08,24.75 16.71,25.38 18.36,25.38 18.98,25.99 18.98,30.97 18.34,31.6 18.34,33.13 19.1,33.89 19.86,33.89 20.37,34.4 20.37,35.58 20.97,36.18 21.26,36.18 21.52,36.43 21.52,38.21 21.77,38.46 22.55,38.46 22.81,38.21 22.81,36.51 23.06,36.25 23.35,36.25 23.55,36.45 23.55,36.73 23.55,36.73 23.55,37.44 23.55,37.45 23.55,37.73 23.55,37.73 23.55,38.44 23.55,38.45 23.55,38.73 23.55,38.73 23.55,39.44 23.55,39.45 23.55,39.73 23.55,39.73 23.55,40.44 23.55,40.45 23.55,40.84 23.97,41.25 24.57,41.25 24.88,40.94 24.88,39.45 24.94,39.38 24.94,38.79 24.88,38.73 24.88,38.45 24.94,38.38 24.94,37.79 24.88,37.73 24.88,34.45 25.08,34.25 25.35,34.25 25.58,34.48 25.58,41.88 25.87,42.17 25.96,42.17 25.97,42.18 26.46,42.18 26.73,41.91 26.85,41.79 26.85,38.46 27.12,38.19 28.23,38.19 28.29,38.25 28.35,38.25 28.55,38.45 28.55,42.02 28.79,42.25 29.65,42.25 29.88,42.02 29.88,37.17 29.64,36.94 27.23,36.94 27.22,36.92 27.08,36.92 26.85,36.7 26.85,35.06 26.84,35.05 26.84,34.96 v1(27.22,34.59)
  BOTTOM w0.089: v1(14.28,20.94) 13.9,21.32 13.64,21.32 13.3,20.97 JX3.26
IO_L03_13_JX2_N: length 73.2
  TOP w0.089: U1.AE26 v1(22.22,17.59)
  L3_SIG w0.089: v1(30.28,14.46) 30.15,14.33 26.07,14.33 25.81,14.58 25.81,15.1 25.45,15.46 25.45,16.75 24.82,17.38 24.82,34.91 24.47,35.25 23.93,35.25 23.55,34.87 23.55,25.35 23.38,25.18 22.97,25.18 22.81,25.35 22.81,27.83 22.8,27.84 22.8,28.34 22.81,28.34 22.81,28.83 22.8,28.84 22.8,29.34 22.81,29.34 22.81,29.83 22.8,29.84 22.8,31.34 22.81,31.34 22.81,31.83 22.8,31.84 22.8,32.34 22.81,32.34 22.81,32.83 22.8,32.84 22.8,33.34 22.81,33.34 22.81,33.83 22.8,33.84 22.8,34.34 22.81,34.34 22.81,34.83 22.8,34.84 22.8,34.87 22.42,35.25 21.97,35.25 21.62,34.91 21.62,18.16 21.84,17.94 22.1,17.94 22.15,17.89 22.15,17.65 v1(22.22,17.59)
  L19_GND w0.089: v4(33.45,13.19) 33.33,13.32 33.33,13.49 33.4,13.57 33.4,13.72 33.33,13.8 33.33,13.95 32.95,14.33 30.41,14.33 v1(30.28,14.46)
  BOTTOM w0.089: JX2.7 33.53,11.95 33.36,12.12 33.36,13.09 v4(33.45,13.19)
IO_L03_13_JX2_P: length 73.3
  TOP w0.089: U1.AE25 v1(22.22,18.59)
  L3_SIG w0.089: v1(30.28,13.95) 30.15,14.08 25.96,14.08 25.56,14.48 25.56,14.99 25.2,15.35 25.2,16.64 24.56,17.28 24.56,34.8 24.37,35 24.04,35 23.81,34.77 23.81,25.24 23.49,24.93 22.87,24.93 22.55,25.24 22.55,27.73 22.55,27.73 22.55,28.45 22.55,28.45 22.55,28.73 22.55,28.73 22.55,29.45 22.55,29.45 22.55,29.73 22.55,29.73 22.55,31.45 22.55,31.45 22.55,31.73 22.55,31.73 22.55,32.45 22.55,32.45 22.55,32.73 22.55,32.73 22.55,33.45 22.55,33.45 22.55,33.73 22.55,33.73 22.55,34.45 22.55,34.45 22.55,34.73 22.55,34.73 22.55,34.77 22.32,35 22.08,35 21.88,34.8 21.88,18.27 21.95,18.2 22.2,18.2 22.4,17.99 22.52,17.99 22.67,18.14 22.67,18.51 22.53,18.65 22.28,18.65 v1(22.22,18.59)
  L19_GND w0.089: v1(30.28,13.95) 30.41,14.08 32.84,14.08 33.07,13.85 33.07,13.32 v4(32.95,13.19)
  BOTTOM w0.089: v4(32.95,13.19) 33.14,12.99 33.14,12.12 32.73,11.7 JX2.5
IO_L03_33_JX1_N: length 74
  TOP w0.089: U1.F2 v1(42.22,42.59)
  L4_SIG w0.089: v1(42.22,42.59) 41.84,42.22 41.84,41.16 41.61,40.92 41.08,40.92 40.81,40.65 40.81,40.34 40.39,39.92 40.08,39.92 39.88,39.73 39.88,39.42 39.39,38.92 39.08,38.92 38.88,38.73 38.88,38.42 38.42,37.95 36.01,37.95 35.63,38.34 35.63,38.47 35.56,38.53 35.56,45.5 36.12,46.06 36.12,46.36 35.63,46.84 32.4,46.84 32.32,46.93 32.04,46.93 31.96,46.84 30.02,46.84 29.77,47.1 29.77,47.86 30.02,48.11 37.35,48.11 37.63,48.39 38.17,48.39 38.44,48.11 38.88,48.11 39.15,48.39 39.69,48.39 39.97,48.11 40.4,48.11 40.68,48.39 41.22,48.39 41.49,48.11 41.86,48.11 41.96,48.22 41.96,48.9 41.86,49 33.96,49 33.71,49.26 33.71,51.54 33.96,51.8 36.35,51.8 36.73,51.42 37.28,51.42 37.67,51.8 40.92,51.8 41.33,51.39 41.33,50.51 41.43,50.4 42.87,50.4 42.98,50.51 42.98,53.07 43.23,53.32 44.38,53.32 44.63,53.07 44.63,52.05 44.88,51.8 47.68,51.8 47.93,51.54 v1(47.93,49.64)
  BOTTOM w0.089: v1(47.93,49.64) 47.61,49.96 47.61,50 47.93,50.32 JX1.44
IO_L03_33_JX1_P: length 73.9
  TOP w0.089: U1.G2 v1(41.22,42.59)
  L4_SIG w0.089: v1(47.17,49.64) 47.46,49.64 47.68,49.86 47.68,50.27 47.55,50.4 47.04,50.4 46.89,50.53 46.89,50.78 47.04,50.91 47.55,50.91 47.68,51.04 47.68,51.42 47.55,51.54 44.78,51.54 44.38,51.95 44.38,52.96 44.27,53.07 43.34,53.07 43.23,52.96 43.23,50.4 42.98,50.15 41.33,50.15 41.07,50.4 41.07,51.29 40.82,51.54 37.77,51.54 37.39,51.16 36.63,51.16 36.25,51.54 34.07,51.54 33.96,51.44 33.96,49.36 34.07,49.26 41.96,49.26 42.22,49 42.22,48.11 41.96,47.86 41.38,47.86 41.11,48.13 40.78,48.13 40.51,47.86 39.86,47.86 39.59,48.13 39.26,48.13 38.98,47.86 38.34,47.86 38.06,48.13 37.73,48.13 37.46,47.86 30.13,47.86 30.02,47.76 30.02,47.2 30.13,47.1 31.86,47.1 31.94,47.18 32.43,47.18 32.51,47.1 35.74,47.1 36.37,46.46 36.37,45.96 35.82,45.4 35.82,38.64 35.88,38.58 35.88,38.45 36.12,38.21 38.31,38.21 38.62,38.52 38.62,38.83 38.97,39.18 39.28,39.18 39.62,39.52 39.62,39.83 39.97,40.18 40.28,40.18 40.55,40.45 40.55,40.76 40.97,41.18 41.5,41.18 41.59,41.26 41.59,42.29 41.48,42.4 41.4,42.4 v1(41.22,42.59)
  BOTTOM w0.089: v1(47.17,49.64) 47.4,49.87 47.4,50.05 47.13,50.32 JX1.42
IO_L03_34_JX4_N: length 72.2
  TOP w0.089: U1.G9 v1(41.22,35.59)
  L17_SIG w0.089: v1(84.38,40.24) 84.19,40.05 84.06,40.05 84,40.11 84,40.37 83.75,40.62 82.88,40.62 81.55,41.95 81.55,44.18 81.17,44.56 81.08,44.56 80.7,44.94 80.7,46.72 81.08,47.1 81.17,47.1 81.55,47.48 81.55,48.68 81.23,49 80.44,49 79.68,48.24 79.17,48.24 78.79,48.62 78.79,51.69 78.43,52.05 77.88,52.05 76.9,51.07 62.79,51.07 61.74,50.02 61.14,50.02 60.09,51.07 50.23,51.07 48.81,49.65 48.81,48.25 48.43,47.87 46.4,47.87 46.26,47.74 46.26,47.27 44.48,45.49 42.49,45.49 40.82,43.82 40.82,36.18 40.84,36.16 40.84,35.96 v1(41.22,35.59)
  BOTTOM w0.089: v1(84.38,40.24) 84.55,40.41 84.76,40.41 85,40.17 JX4.27
IO_L03_34_JX4_P: length 72.6
  TOP w0.089: U1.H9 v1(40.22,35.59)
  L17_SIG w0.089: v1(40.22,35.59) 40.59,35.96 40.59,36.05 40.57,36.07 40.57,43.92 42.38,45.74 44.38,45.74 46.01,47.37 46.01,47.84 46.29,48.13 48.32,48.13 48.56,48.36 48.56,49.75 50.13,51.33 60.19,51.33 61.24,50.27 61.63,50.27 62.68,51.33 76.8,51.33 77.78,52.31 78.54,52.31 79.05,51.8 79.05,48.73 79.28,48.5 79.58,48.5 80.34,49.26 81.33,49.26 81.8,48.79 81.8,47.37 81.27,46.84 81.18,46.84 80.95,46.61 80.95,45.04 81.18,44.81 81.27,44.81 81.8,44.28 81.8,42.06 82.98,40.88 v1(84.38,40.88)
  BOTTOM w0.089: JX4.25 85.11,40.97 84.76,40.62 84.63,40.62 v1(84.38,40.88) ; v1(40.22,35.59) 39.98,35.35 R53.1
IO_L03_35_RX_D2_N: length 44.2
  TOP w0.089: U1.F10 v1(42.22,34.59) ; v6(62.8,32.89) U17.K9
  L17_SIG w0.089: v1(42.22,34.59) 41.84,34.22 41.84,33.86 41.87,33.84 41.87,33.44 42.07,33.24 42.36,33.24 42.6,33.48 42.6,34.63 42.61,34.65 42.61,34.84 42.97,35.19 45.39,35.19 45.63,35.43 45.63,35.83 45.65,35.85 45.65,36.32 45.63,36.34 45.63,36.83 46.04,37.25 47.35,37.25 47.55,37.45 48.49,37.45 48.89,37.04 48.89,35.39 49,35.29 49.63,35.29 50.09,35.75 50.09,36.43 50.34,36.68 50.73,36.68 50.98,36.43 50.98,36.26 51.23,36.01 51.74,36.01 52,36.26 52,36.94 52.25,37.19 53.01,37.19 53.27,36.94 53.27,36.26 53.52,36.01 54.79,36.01 55.04,35.75 55.04,35.42 55.25,35.21 55.53,35.21 55.58,35.25 56.81,35.25 56.85,35.21 57.13,35.21 57.18,35.25 57.34,35.25 57.75,35.67 60.25,35.67 60.5,35.92 66.09,35.92 66.35,35.67 66.35,35.19 65.94,34.79 65.87,34.79 65.69,34.6 63.98,34.6 63.82,34.44 63.54,34.44 63.38,34.6 62.74,34.6 62.41,34.27 62.28,34.27 62.16,34.14 62.16,34.02 62.3,33.88 62.3,33.88 62.5,33.67 62.5,33.51 62.54,33.51 62.66,33.38 63.04,33.38 63.3,33.13 63.3,33 63.04,32.75 62.94,32.75 v6(62.8,32.89)
IO_L03_35_RX_D2_P: length 44.4
  TOP w0.089: U1.G10 v1(41.22,34.59) ; v6(62,32.09) U17.J10
  L17_SIG w0.089: v1(41.22,34.59) 41.59,34.22 41.59,33.76 41.61,33.73 41.61,33.34 41.97,32.99 42.47,32.99 42.85,33.37 42.85,34.53 42.87,34.54 42.87,34.73 43.07,34.94 45.5,34.94 45.9,35.34 45.9,35.43 45.88,35.45 45.88,35.73 45.9,35.75 45.9,36.43 45.88,36.45 45.88,36.73 46.15,37 47.46,37 47.65,37.19 48.39,37.19 48.64,36.94 48.64,35.29 48.89,35.03 49.74,35.03 50.34,35.64 50.34,36.33 50.45,36.43 50.62,36.43 50.73,36.33 50.73,36.15 51.13,35.75 51.85,35.75 52.25,36.15 52.25,36.83 52.35,36.94 52.91,36.94 53.01,36.83 53.01,36.15 53.41,35.75 54.68,35.75 54.79,35.65 54.79,35.31 55.15,34.95 55.64,34.95 55.68,35 56.7,35 56.75,34.95 57.24,34.95 57.28,35 57.44,35 57.86,35.41 60.36,35.41 60.61,35.67 65.99,35.67 66.09,35.56 66.09,35.3 65.84,35.05 65.77,35.05 65.58,34.86 64.08,34.86 63.82,35.12 63.54,35.12 63.28,34.86 62.64,34.86 62.3,34.53 62.18,34.53 61.9,34.25 61.9,34.02 61.7,33.82 61.7,33.57 61.87,33.39 61.98,33.39 62.24,33.13 62.24,33.07 62.3,33.02 62.3,32.39 v6(62,32.09)
IO_L04_12_JX3_N: length 73.8
  TOP w0.089: U1.AB10 v1(25.22,34.59)
  L6_SIG w0.089: v1(25.22,34.59) 24.84,34.22 21.5,34.22 21.46,34.25 20.73,34.25 20.37,33.89 14.02,33.89 12.63,32.49 12.63,30.06 12.39,29.83 9.17,29.83 8.94,30.06 8.94,47.73 8.69,47.99 7.55,47.99 7.29,47.73 7.29,43.67 7.44,43.52 7.44,43.52 7.65,43.31 7.65,42.38 7.29,42.01 7.29,31.73 6.89,31.33 6.89,30.36 7.42,29.83 7.42,27.79 7.8,27.41 12.24,27.41 12.63,27.03 12.63,24.47 12.12,23.96 10.37,23.96 10.33,23.92 10.23,23.92 10.04,24.11 v1(9.7,24.11)
  BOTTOM w0.089: v1(9.7,24.11) 9.45,23.86 9.2,23.86 8.88,24.17 JX3.33
IO_L04_12_JX3_P: length 73.7
  TOP w0.089: U1.AB11 v1(25.22,33.59)
  L6_SIG w0.089: v1(9.7,23.48) 10.04,23.48 10.23,23.67 10.43,23.67 10.48,23.71 12.22,23.71 12.88,24.37 12.88,27.14 12.35,27.67 7.9,27.67 7.67,27.9 7.67,29.93 7.14,30.46 7.14,31.22 7.55,31.63 7.55,41.91 7.91,42.27 7.91,43.42 7.55,43.78 7.55,47.63 7.65,47.73 8.58,47.73 8.69,47.63 8.69,29.95 9.07,29.57 12.5,29.57 12.88,29.95 12.88,32.39 14.13,33.64 20.48,33.64 20.84,34 21.35,34 21.39,33.96 24.84,33.96 v1(25.22,33.59)
  BOTTOM w0.089: JX3.31 8.98,23.37 9.25,23.64 9.54,23.64 v1(9.7,23.48)
IO_L04_13_JX2_N: length 72.5
  TOP w0.089: U1.AD26 v1(23.22,17.59)
  L14_SIG w0.089: v1(23.22,17.59) 23.29,17.67 23.29,18.02 23.21,18.1 23.08,18.1 22.95,17.96 22.07,17.96 21.88,17.77 21.88,17.4 21.35,16.87 20.19,16.87 20.11,16.79 19.62,16.79 19.54,16.87 18.83,16.87 18.59,16.64 18.59,16.09 18.83,15.86 23.18,15.86 23.55,15.48 23.55,14.96 23.18,14.59 19.21,14.59 18.45,13.82 16.4,13.82 16.18,13.6 16.18,13.29 16.4,13.06 17.19,13.06 17.7,12.55 19.36,12.55 19.46,12.66 19.46,13.04 19.99,13.57 20.5,13.57 21.01,13.06 22.02,13.06 22.4,12.68 22.4,11.54 22.66,11.28 24.94,11.28 25.33,10.9 25.33,9.89 24.82,9.38 22.3,9.38 21.9,9.78 21.9,10.42 21.79,10.52 20.86,10.52 20.75,10.42 20.75,9.91 20.35,9.51 18.83,9.51 18.72,9.4 18.72,8.49 18.83,8.39 20.48,8.39 20.88,7.98 20.88,6.44 20.99,6.33 21.28,6.33 21.39,6.44 21.39,7.86 21.9,8.36 22.64,8.36 22.64,8.36 22.81,8.19 23.97,8.19 24.31,7.86 25.2,7.86 25.45,8.11 25.45,8.87 26.09,9.51 26.09,10.52 26.47,10.9 29.88,10.9 30.41,10.37 30.41,8.72 30.64,8.49 31.19,8.49 31.42,8.72 31.42,10.37 31.95,10.9 32.95,10.9 33.41,10.44 33.41,9.06 v1(33.45,9.01)
  BOTTOM w0.089: v1(33.45,9.01) 33.45,9 33.2,8.74 33.2,8.33 33.21,8.33 33.21,8.05 33.2,8.04 33.2,7.6 33.53,7.27 JX2.8
IO_L04_13_JX2_P: length 72.5
  TOP w0.089: U1.AD25 v1(23.22,18.59)
  L14_SIG w0.089: v1(23.22,18.59) 22.84,18.22 21.97,18.22 21.63,17.87 21.63,17.51 21.24,17.13 20.09,17.13 20,17.04 19.72,17.04 19.64,17.13 18.72,17.13 18.34,16.75 18.34,15.98 18.72,15.6 23.07,15.6 23.29,15.38 23.29,15.06 23.07,14.84 19.1,14.84 18.34,14.08 16.3,14.08 15.93,13.71 15.93,13.18 16.3,12.81 17.08,12.81 17.59,12.3 19.46,12.3 19.72,12.55 19.72,12.94 20.1,13.32 20.39,13.32 20.9,12.81 21.92,12.81 22.15,12.58 22.15,11.43 22.55,11.03 24.84,11.03 25.07,10.8 25.07,9.99 24.71,9.63 22.4,9.63 22.15,9.89 22.15,10.52 21.9,10.78 20.75,10.78 20.5,10.52 20.5,10.01 20.25,9.76 18.72,9.76 18.47,9.51 18.47,8.39 18.72,8.13 20.37,8.13 20.63,7.88 20.63,6.33 20.88,6.08 21.39,6.08 21.64,6.33 21.64,7.75 22,8.11 22.53,8.11 22.7,7.94 23.87,7.94 24.2,7.6 25.3,7.6 25.71,8 25.71,8.77 26.34,9.4 26.34,10.42 26.57,10.65 29.77,10.65 30.15,10.27 30.15,8.62 30.53,8.24 31.29,8.24 31.68,8.62 31.68,10.27 32.06,10.65 32.84,10.65 33.15,10.34 33.15,9.49 33.07,9.41 33.07,9.25 v1(32.82,9)
  BOTTOM w0.089: v1(32.82,9) 32.98,8.83 32.98,7.67 32.73,7.42 JX2.6
IO_L04_33_JX1_N: length 73.8
  TOP w0.089: U1.C1 v1(45.22,43.59)
  L7_SIG w0.089: v1(50.34,56.88) 50.09,56.62 50.09,55.86 50.47,55.48 50.73,55.48 51.11,55.86 51.11,57.77 50.73,58.15 48.73,58.15 48.1,58.77 48.1,59.46 48.82,60.18 49.33,60.18 49.58,60.43 50.98,60.43 51.23,60.18 57.08,60.18 57.46,59.8 57.46,58.3 56.93,57.77 53.8,57.77 53.56,57.53 53.56,57.42 53.31,57.17 53.31,55.1 53.69,54.72 56.19,54.72 56.57,54.34 56.57,53.83 56.19,53.45 53.62,53.45 53.39,53.22 53.39,53.15 53.31,53.07 53.31,52.66 53.54,52.43 53.68,52.43 53.69,52.42 57.37,52.42 57.7,52.1 57.98,52.1 58.3,52.42 63.3,52.42 63.68,52.04 63.68,50.53 63.3,50.15 63.04,50.15 62.66,49.77 62.66,48.37 62.28,47.99 55.93,47.99 54.92,46.97 53.27,46.97 52.38,47.86 48.51,47.86 47.79,47.14 47.79,46.32 45.77,44.3 45.1,44.3 44.84,44.05 44.84,43.96 v1(45.22,43.59)
  BOTTOM w0.089: JX1.49 50.33,56.26 50.09,56.5 50.09,56.62 v1(50.34,56.88)
IO_L04_33_JX1_P: length 73.8
  TOP w0.089: U1.D1 v1(44.22,43.59)
  L7_SIG w0.089: v1(44.22,43.59) 44.59,43.96 44.59,44.16 44.99,44.56 45.67,44.56 47.53,46.42 47.53,47.24 48.4,48.11 52.48,48.11 53.37,47.23 54.81,47.23 55.83,48.24 62.18,48.24 62.41,48.47 62.41,49.87 62.94,50.4 63.19,50.4 63.43,50.63 63.43,51.93 63.19,52.17 58.41,52.17 58.08,51.84 57.59,51.84 57.27,52.17 53.59,52.17 53.57,52.18 53.44,52.18 53.06,52.56 53.06,53.17 53.14,53.26 53.14,53.32 53.52,53.7 53.59,53.7 56.08,53.7 56.31,53.93 56.31,54.23 56.08,54.46 53.59,54.46 53.06,54.99 53.06,57.28 53.31,57.53 53.31,57.64 53.69,58.02 56.82,58.02 57.2,58.4 57.2,59.69 56.97,59.93 51.13,59.93 50.87,60.18 49.69,60.18 49.43,59.93 48.93,59.93 48.36,59.36 48.36,58.88 48.83,58.4 50.83,58.4 51.36,57.87 51.36,55.76 50.83,55.23 50.37,55.23 49.84,55.76 49.84,56.62 v1(49.58,56.88)
  BOTTOM w0.089: v1(49.58,56.88) 49.84,56.62 49.84,56.5 49.53,56.19 JX1.47
IO_L04_34_JX4_N: length 73.6
  TOP w0.089: U1.H6 v1(40.22,38.59)
  L4_SIG w0.089: v1(80.19,40.49) 80.55,40.49 80.81,40.24 82.98,40.24 83.88,41.14 84.13,41.38 85.14,41.38 85.9,42.15 85.9,44.56 86.29,44.94 87.56,44.94 87.81,44.69 87.81,44.43 88.06,44.18 88.95,44.18 89.21,44.43 89.21,46.46 88.95,46.72 83.24,46.72 82.86,46.34 82.86,43.29 81.33,41.76 79.81,41.76 78.56,40.51 75.51,40.51 75.11,40.11 73.82,40.11 73.42,40.51 72.19,40.51 71.7,41 67.24,41 66.45,40.22 59.67,40.22 59.51,40.37 56.58,40.37 56.33,40.62 55.25,40.62 54.67,40.03 52.24,40.03 51.65,40.62 50.45,40.62 50.03,40.19 50.03,40.16 49.05,39.18 44.97,39.18 44.55,38.76 44.55,38.45 44.32,38.22 40.59,38.22 v1(40.22,38.59)
  BOTTOM w0.089: v1(80.19,40.49) 80.48,40.49 80.8,40.17 JX4.28
IO_L04_34_JX4_P: length 73.6
  TOP w0.089: U1.H7 v1(40.22,37.59)
  L4_SIG w0.089: v1(80.19,41) 80.55,41 81.06,40.49 81.59,40.49 81.71,40.62 81.71,41.13 81.84,41.26 82.22,41.26 82.35,41.13 82.35,40.62 82.48,40.49 82.88,40.49 83.11,40.73 83.11,41.13 83.3,41.32 83.7,41.32 84.02,41.64 85.04,41.64 85.65,42.25 85.65,44.66 86.18,45.19 87.66,45.19 88.06,44.79 88.06,44.54 88.17,44.43 88.85,44.43 88.95,44.54 88.95,46.36 88.85,46.46 83.34,46.46 83.11,46.23 83.11,43.18 81.44,41.51 79.91,41.51 78.66,40.26 75.62,40.26 75.22,39.86 73.71,39.86 73.31,40.26 72.08,40.26 71.59,40.75 67.34,40.75 66.55,39.96 59.56,39.96 59.41,40.11 56.58,40.11 56.24,39.78 50.01,39.78 49.16,38.92 45.08,38.92 44.81,38.65 44.81,38.34 44.42,37.96 40.52,37.96 40.41,37.85 40.41,37.79 v1(40.22,37.59)
  BOTTOM w0.089: JX4.26 80.79,40.97 80.7,40.88 80.28,40.88 80.19,40.96 v1(80.19,41)
IO_L04_35_RX_D3_N: length 41.4
  TOP w0.089: v6(63.6,32.89) U17.K8 ; U1.D11 v1(44.22,33.59)
  L6_SIG w0.089: v1(44.22,33.59) 43.94,33.59 43.81,33.46 43.81,33.27 43.46,32.93 42.97,32.93 42.62,33.27 42.62,33.84 42.46,34 42.08,34 41.81,33.73 41.81,33.34 41.46,33 41.46,33 41.38,32.92 40.08,32.92 39.88,32.73 39.88,32.52 39.81,32.44 39.81,32.34 39.46,32 38.91,32 38.81,31.91 38.81,31.42 38.81,31.42 38.81,31.34 38.08,30.61 37.42,30.61 37.31,30.51 37.31,30.25 37.39,30.18 39.55,30.18 39.68,30.31 39.71,30.31 40.56,31.15 40.56,31.77 40.97,32.18 41.06,32.18 41.12,32.24 50.98,32.24 51.49,31.73 52.02,31.73 52.52,32.24 52.99,32.24 53.24,31.99 53.95,31.99 54.04,32.07 54.53,32.07 54.61,31.99 55.02,31.99 55.28,31.73 56.23,31.73 56.44,31.94 56.96,31.94 57.05,31.94 58.07,32.96 58.07,33.36 58.35,33.64 59.72,33.64 60.17,33.19 62.97,33.19 63.1,33.05 63.1,32.94 63.17,32.87 63.41,32.87 63.43,32.89 v6(63.6,32.89)
IO_L04_35_RX_D3_P: length 43.4
  TOP w0.089: U1.E11 v1(43.22,33.59) ; v6(62.8,32.09) U17.J9
  L6_SIG w0.089: v1(43.22,33.59) 43.21,33.6 43.21,34.12 43.31,34.22 43.56,34.22 43.74,34.05 43.74,33.74 43.56,33.56 43.56,33.38 43.36,33.18 43.08,33.18 42.88,33.38 42.88,33.94 42.57,34.25 41.97,34.25 41.55,33.83 41.55,33.45 41.35,33.25 41.35,33.25 41.28,33.18 39.97,33.18 39.63,32.83 39.63,32.62 39.55,32.55 39.55,32.45 39.35,32.25 38.8,32.25 38.56,32.01 38.56,31.53 38.55,31.52 38.55,31.45 37.97,30.87 37.31,30.87 37.06,30.61 37.06,30.15 37.28,29.92 39.66,29.92 39.78,30.05 39.82,30.05 40.82,31.05 40.82,31.66 41.08,31.92 41.16,31.92 41.23,31.99 50.87,31.99 51.38,31.48 52.12,31.48 52.63,31.99 52.88,31.99 53.14,31.73 54.06,31.73 54.14,31.81 54.42,31.81 54.5,31.73 54.92,31.73 55.17,31.48 56.34,31.48 56.55,31.69 57.06,31.69 57.16,31.69 58.32,32.85 58.32,33.26 58.45,33.38 59.62,33.38 60.01,32.99 60.01,32.86 60.27,32.6 60.38,32.6 62.94,32.59 63.03,32.5 63.17,32.36 63.17,32.24 63.03,32.09 v6(62.8,32.09)
IO_L05_12_JX3_N: length 73.6
  TOP w0.089: U1.Y13 v1(27.22,31.59)
  L6_SIG w0.089: v1(15.55,28.43) 15.67,28.56 15.8,28.56 15.93,28.43 16,28.43 16.13,28.56 16.13,28.73 15.93,28.94 15.93,28.99 16.13,29.19 16.13,29.4 16.56,29.83 17.71,29.83 18.09,29.45 18.09,21.21 17.56,20.68 15.91,20.68 15.67,20.45 15.67,19.31 15.17,18.8 15.17,17.1 15.42,16.85 15.42,15.58 14.89,15.05 14.46,15.05 14.15,14.74 14.15,13.8 15.29,12.66 15.29,11.9 15.59,11.6 15.59,8.09 15.83,7.86 17.22,7.86 17.45,8.09 17.45,10.37 18.21,11.14 18.21,12.66 18.62,13.06 21.64,13.06 22.02,13.44 22.02,14.33 21.64,14.71 19.23,14.71 18.85,15.09 18.85,29.87 19.23,30.25 26.35,30.25 26.44,30.33 27.25,30.33 27.61,30.69 27.61,31.3 27.51,31.4 27.4,31.4 v1(27.22,31.59)
  BOTTOM w0.089: JX3.44 13.26,28.17 13.64,27.79 14.02,27.79 14.4,28.18 15.29,28.18 v1(15.55,28.43)
IO_L05_12_JX3_P: length 73.7
  TOP w0.089: U1.W13 v1(28.22,31.59)
  L6_SIG w0.089: v1(16.02,28.09) 16.14,28.21 16.18,28.25 16.39,28.45 16.39,29.29 16.67,29.57 17.6,29.57 17.83,29.34 17.83,21.32 17.45,20.94 15.8,20.94 15.42,20.56 15.42,19.41 14.91,18.9 14.91,17 15.17,16.75 15.17,15.69 14.78,15.3 14.36,15.3 13.9,14.84 13.9,13.7 15.04,12.55 15.04,11.79 15.34,11.49 15.34,7.98 15.72,7.6 17.32,7.6 17.71,7.98 17.71,10.27 18.47,11.03 18.47,12.55 18.72,12.81 21.75,12.81 22.28,13.34 22.28,14.44 21.75,14.97 19.33,14.97 19.1,15.2 19.1,29.77 19.33,30 26.46,30 26.54,30.08 27.36,30.08 27.87,30.59 27.87,31.24 v1(28.22,31.59)
  BOTTOM w0.089: v1(16.02,28.09) 15.51,28.09 15.38,27.96 14.49,27.96 14.11,27.58 13.55,27.58 13.49,27.64 13.22,27.37 JX3.42
IO_L05_33_JX1_N: length 72.6
  TOP w0.089: U1.E1 v1(43.22,43.59)
  L14_SIG w0.089: v1(52.63,49.64) 52.5,49.77 52.5,50.42 52.27,50.65 51.38,50.65 50.98,50.25 50.98,48.28 51.51,47.75 53.05,47.75 53.39,47.41 53.39,46.95 53.16,46.72 50.58,46.72 50.34,46.95 50.34,48.24 49.96,48.62 48.97,48.62 48.59,48.24 48.59,45.89 48.57,45.87 48.57,45.32 49.46,44.43 50.33,44.43 50.45,44.55 52.48,44.55 52.6,44.43 54.03,44.43 54.15,44.55 56.33,44.55 56.45,44.43 57.48,44.43 57.71,44.2 57.71,43.03 58.09,42.65 58.9,42.65 59.28,43.03 59.28,43.08 59.66,43.46 60.24,43.46 60.59,43.81 60.59,44.22 60.8,44.43 61.1,44.43 61.31,44.22 61.31,43.94 61.61,43.64 62.11,43.64 63.66,45.19 65.82,45.19 67.33,46.71 67.64,46.71 67.86,46.49 67.86,46.18 66.24,44.56 64.21,44.56 62.71,43.06 62.31,43.06 61.01,41.76 57.18,41.76 56.35,42.6 56.35,42.6 56.06,42.89 55.55,42.89 55.19,42.53 54.39,42.53 54.13,42.78 52.76,42.78 52.5,43.03 50.47,43.03 50.22,42.78 48.33,42.78 47.73,42.18 45.08,42.18 44.81,42.45 44.81,42.83 44.42,43.22 43.59,43.22 v1(43.22,43.59)
  BOTTOM w0.089: v1(52.63,49.64) 52.44,49.83 52.44,50.01 52.73,50.3 JX1.56
IO_L05_33_JX1_P: length 72.5
  TOP w0.089: U1.E2 v1(43.22,42.59)
  L14_SIG w0.089: v1(52,49.64) 52.25,49.89 52.25,50.31 52.16,50.4 51.49,50.4 51.23,50.15 51.23,48.39 51.61,48.01 53.15,48.01 53.65,47.51 53.65,46.84 53.27,46.46 50.47,46.46 50.09,46.84 50.09,48.14 49.86,48.37 49.07,48.37 48.84,48.14 48.84,45.79 48.82,45.77 48.82,45.43 49.56,44.69 50.23,44.69 50.35,44.81 52.58,44.81 52.7,44.69 53.93,44.69 54.05,44.81 56.44,44.81 56.56,44.69 57.58,44.69 57.96,44.3 57.96,43.14 58.2,42.91 58.79,42.91 59.02,43.14 59.02,43.18 59.55,43.71 60.14,43.71 60.33,43.91 60.33,44.32 60.69,44.69 61.2,44.69 61.56,44.32 61.56,44.04 61.71,43.9 62,43.9 63.55,45.45 65.71,45.45 67.23,46.97 67.75,46.97 68.12,46.6 68.12,46.08 66.35,44.3 64.31,44.3 62.81,42.8 62.41,42.8 61.12,41.51 57.08,41.51 56.17,42.42 56.09,42.49 56.09,42.5 55.96,42.63 55.66,42.63 55.29,42.27 54.28,42.27 54.03,42.53 52.73,42.53 52.52,42.32 50.47,42.32 50.26,42.53 48.44,42.53 47.84,41.92 44.97,41.92 44.55,42.34 44.55,42.73 44.32,42.96 43.48,42.96 43.38,43.06 43.26,43.06 43.17,42.97 43.17,42.63 v1(43.22,42.59)
  BOTTOM w0.089: JX1.54 51.93,50.21 52.22,49.92 52.22,49.86 v1(52,49.64)
IO_L05_34_JX4_N: length 73.2
  TOP w0.089: U1.J9 v1(39.22,35.59)
  L14_SIG w0.089: v1(39.22,35.59) 39.59,35.22 43.32,35.22 43.55,35.45 43.55,35.76 43.97,36.18 47.93,36.18 48.82,37.07 49.3,37.07 49.65,37.41 51.53,37.41 51.88,37.07 53.93,37.07 54.19,36.81 56.69,36.81 56.75,36.87 57.24,36.87 57.29,36.81 57.86,36.81 58.24,37.19 60.05,37.19 60.13,37.27 60.62,37.27 60.7,37.19 70.11,37.19 70.22,37.3 70.22,38.82 70.62,39.22 73.94,39.22 74.47,38.69 74.47,37.17 74.71,36.94 76.27,36.94 76.51,37.17 76.51,40.85 77.04,41.38 78.01,41.38 78.54,40.85 78.54,39.61 78.92,39.22 80.42,39.22 80.95,38.69 80.95,33.61 81.18,33.38 81.86,33.38 82.09,33.61 82.09,38.69 82.62,39.22 85.52,39.22 85.9,38.84 85.9,38.42 85.52,38.04 84.58,38.04 v1(84.38,37.84)
  BOTTOM w0.089: v1(84.38,37.84) 84.55,38.01 84.76,38.01 85,37.77 JX4.33
IO_L05_34_JX4_P: length 73.3
  TOP w0.089: U1.J10 v1(39.22,34.59)
  L14_SIG w0.089: v1(39.22,34.59) 38.97,34.59 38.97,34.6 38.79,34.78 38.79,34.91 38.97,35.09 39.35,35.09 39.48,34.96 43.42,34.96 43.81,35.34 43.81,35.65 44.08,35.92 48.04,35.92 48.93,36.81 49.58,36.81 49.65,36.74 51.53,36.74 51.6,36.81 53.83,36.81 54.09,36.55 56.79,36.55 56.85,36.61 57.13,36.61 57.19,36.56 57.96,36.56 58.35,36.94 60.16,36.94 60.24,37.02 60.52,37.02 60.6,36.94 70.22,36.94 70.47,37.19 70.47,38.72 70.73,38.97 73.84,38.97 74.22,38.59 74.22,37.07 74.6,36.68 76.38,36.68 76.76,37.07 76.76,40.75 77.14,41.13 77.9,41.13 78.28,40.75 78.28,39.5 78.81,38.97 80.32,38.97 80.7,38.59 80.7,33.51 81.08,33.13 81.97,33.13 82.35,33.51 82.35,38.59 82.73,38.97 85.42,38.97 85.65,38.74 85.65,38.52 85.42,38.29 84.57,38.29 v1(84.38,38.48)
  BOTTOM w0.089: v1(84.38,38.48) 84.63,38.22 84.76,38.22 85.11,38.57 85.95,38.57 JX4.31
IO_L05_35_RX_D4_N: length 43.9
  TOP w0.089: U1.G11 v1(41.22,33.59) ; v6(64.4,32.89) U17.K7
  L4_SIG w0.089: v1(41.22,33.59) 41.21,33.59 40.87,33.59 40.77,33.48 40.77,33.1 40.89,32.98 41.25,32.98 41.48,33.22 42.32,33.22 42.6,33.49 42.6,33.99 42.86,34.25 43.61,34.25 43.88,33.98 43.88,33.45 44.08,33.25 44.47,33.25 44.58,33.36 44.58,33.85 44.98,34.25 45.57,34.25 45.88,33.94 45.88,33.45 46.08,33.25 46.35,33.25 46.55,33.45 46.55,33.86 46.89,34.2 47.55,34.2 47.81,33.94 47.81,33.47 48.06,33.22 48.4,33.22 48.82,33.64 50.42,33.64 50.45,33.61 51.33,33.61 51.92,34.2 53.03,34.2 53.77,34.94 53.77,35.38 54.18,35.79 54.76,35.79 55.06,35.49 55.06,35.4 55.25,35.21 57.33,35.21 57.74,34.8 57.74,34.63 57.84,34.53 57.99,34.53 58.24,34.78 58.24,36.22 58.48,36.46 58.82,36.46 59.06,36.22 59.06,34.78 59.31,34.53 59.64,34.53 59.74,34.63 59.74,36.07 59.97,36.3 60.72,36.3 60.95,36.07 60.95,34.65 61.2,34.4 62.2,34.4 62.31,34.5 62.31,35.19 62.66,35.54 64.57,35.54 64.82,35.29 64.82,34.78 64.57,34.53 64.31,34.53 63.93,34.14 63.93,33.78 63.94,33.77 63.97,33.77 64.1,33.64 64.1,33.57 64.27,33.4 64.68,33.4 64.82,33.26 64.82,33.02 64.7,32.89 v6(64.4,32.89)
IO_L05_35_RX_D4_P: length 42.7
  TOP w0.089: U1.G12 v1(41.22,32.59) ; v6(63.6,32.09) U17.J8
  L4_SIG w0.089: v1(41.22,32.59) 41.59,32.96 42.42,32.96 42.85,33.39 42.85,33.89 42.96,34 43.5,34 43.63,33.87 43.63,33.34 43.97,33 44.58,33 44.83,33.25 44.83,33.74 45.09,34 45.46,34 45.63,33.83 45.63,33.34 45.97,33 46.46,33 46.81,33.34 46.81,33.75 47,33.94 47.45,33.94 47.55,33.84 47.55,33.31 47.9,32.96 48.5,32.96 48.93,33.38 50.32,33.38 50.35,33.35 51.44,33.35 52.02,33.94 53.14,33.94 54.03,34.83 54.03,35.28 54.28,35.53 54.65,35.53 54.8,35.38 54.8,35.3 55.15,34.95 57.23,34.95 57.48,34.7 57.48,34.53 57.74,34.27 58.1,34.27 58.5,34.67 58.5,36.11 58.59,36.2 58.71,36.2 58.8,36.11 58.8,34.67 59.21,34.27 59.74,34.27 60,34.53 60,35.97 60.08,36.05 60.61,36.05 60.69,35.97 60.69,34.55 61.1,34.14 62.31,34.14 62.56,34.4 62.56,35.08 62.77,35.29 64.46,35.29 64.57,35.18 64.57,34.88 64.46,34.78 64.21,34.78 63.68,34.25 63.68,34.12 63.55,33.99 63.47,33.99 63.3,33.82 63.3,33.57 63.65,33.22 63.8,33.22 63.89,33.13 63.89,32.77 63.6,32.47 v6(63.6,32.09)
IO_L06_12_JX3_N: length 72.1
  TOP w0.089: U1.AA12 v1(26.22,32.59)
  L7_SIG w0.089: v1(15.5,37.95) 15.55,37.95 15.59,37.91 16.93,37.91 17.28,37.56 17.28,37.12 17.32,37.07 17.32,34.73 17.41,34.64 17.41,34.14 17.53,34.02 18.34,34.02 18.47,34.14 18.47,35.83 18.55,35.91 18.55,36.19 18.47,36.27 18.47,37.73 18.49,37.75 18.49,38.03 18.47,38.05 18.47,38.62 18.55,38.7 18.55,38.98 18.47,39.07 18.47,40.14 18.95,40.62 19.63,40.62 20.12,40.14 20.12,38.66 20.2,38.58 20.2,38.09 20.12,38.01 20.12,36.53 20.04,36.44 20.04,36.16 20.12,36.08 20.12,34.73 20.2,34.64 20.2,34.15 20.12,34.07 20.12,32.06 20.2,31.98 20.2,27.39 20.43,27.16 20.95,27.16 20.97,27.18 21.18,27.18 21.25,27.25 21.35,27.25 21.55,27.45 21.55,33.89 21.91,34.25 22.46,34.25 22.88,33.83 22.88,33.45 22.91,33.42 22.91,32.76 22.88,32.73 22.88,32.45 22.91,32.42 22.91,31.76 22.88,31.73 22.88,27.39 23.09,27.18 23.46,27.18 23.48,27.16 23.95,27.16 23.97,27.18 24.41,27.18 24.62,27.39 24.62,27.83 24.97,28.18 25.46,28.18 25.46,28.18 25.97,28.18 25.97,28.18 26.46,28.18 26.53,28.1 26.66,27.98 26.85,27.79 26.85,25.36 27.03,25.18 28.32,25.18 28.63,25.48 28.63,28.19 28.62,28.71 28.39,28.94 28.27,28.94 28.21,29 27.97,29 27.62,29.34 27.62,30.22 27.38,30.46 26.95,30.46 26.85,30.36 26.85,29.47 26.81,29.42 26.81,29.34 26.46,29 26.38,29 26.32,28.94 25.15,28.94 25.09,29 24.97,29 24.62,29.34 24.62,31.83 24.97,32.18 25.35,32.18 25.43,32.19 25.45,32.22 25.84,32.22 v1(26.22,32.59)
  BOTTOM w0.089: v1(15.5,37.95) 15.5,37.9 15.29,37.7 14.4,37.7 14.02,37.32 14.02,36.81 13.86,36.65 13.51,36.65 13.19,36.97 JX3.66
